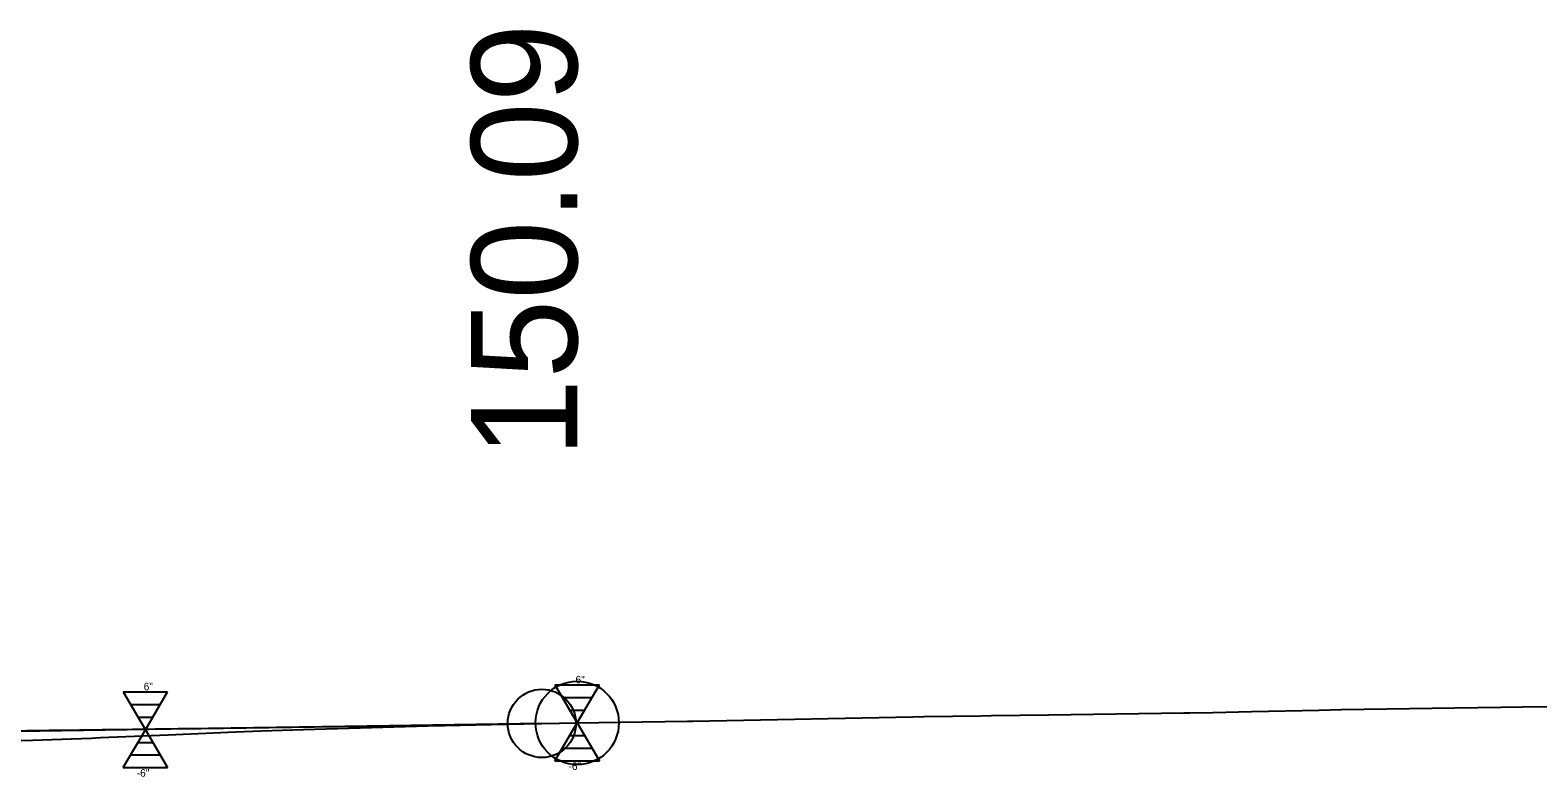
# Model space of a CAD drawing. Extents: x 573468 to 580768, y -57414 to -51768.
# Drawn here: x 575797.7 to 575897.1, y -53383.4 to -53334.2 of the extents above; entities that cross this region are included whole.
import ezdxf

# ---------------------------------------------------------------- set-up
doc = ezdxf.new("R2010")
doc.units = 0
for name, color, linetype in [('Exist Vertical Profile Ground Line', 7, 'Continuous'), ('Pattern 2', 7, 'Continuous'), ('Prop Vertical Profile Curve Label', 7, 'Continuous'), ('Prop Vertical Profile Grade', 7, 'Continuous'), ('Prop VPI Label', 7, 'Continuous')]:
    doc.layers.add(name, color=color, linetype=linetype)

msp = doc.modelspace()

# ---------------------------------------------------------------- linework, layer by layer
at = {"layer": 'Exist Vertical Profile Ground Line'}
msp.add_lwpolyline([(575793.37, -53381.119), (575797.837, -53380.998), (575801.709, -53380.869), (575802.304, -53380.843), (575806.771, -53380.652), (575811.238, -53380.464), (575812.905, -53380.395), (575815.705, -53380.311), (575820.18, -53380.179), (575824.639, -53380.044), (575825.021, -53380.032), (575829.106, -53379.952), (575833.758, -53379.863), (575838.039, -53379.802), (575841.041, -53379.759), (575841.381, -53379.753), (575842.506, -53379.73), (575846.973, -53379.64), (575851.44, -53379.552), (575855.907, -53379.464), (575856.642, -53379.45), (575860.374, -53379.395), (575861.097, -53379.384), (575864.841, -53379.33), (575869.308, -53379.266), (575873.775, -53379.203), (575874.162, -53379.198), (575875.686, -53379.177), (575878.241, -53379.122), (575882.708, -53379.028), (575884.155, -53378.997), (575887.175, -53378.95), (575891.642, -53378.882), (575894.683, -53378.837), (575896.109, -53378.82), (575900.576, -53378.768)], dxfattribs=at)
at = {"layer": 'Pattern 2'}
for p, q in [((575803.811, -53377.818), (575806.744, -53377.818)), ((575803.811, -53377.818), (575805.278, -53380.318)), ((575805.278, -53380.318), (575806.744, -53377.818)), ((575832.291, -53377.368), (575835.224, -53377.368)), ((575832.291, -53377.368), (575833.758, -53379.868)), ((575833.758, -53379.868), (575835.224, -53377.368)), ((575804.3, -53378.652), (575806.255, -53378.652)), ((575832.78, -53378.202), (575834.735, -53378.202)), ((575804.789, -53379.485), (575805.766, -53379.485)), ((575833.269, -53379.035), (575834.246, -53379.035)), ((575803.811, -53382.818), (575805.278, -53380.318)), ((575805.278, -53380.318), (575806.744, -53382.818)), ((575832.291, -53382.368), (575833.758, -53379.868)), ((575833.269, -53380.702), (575834.246, -53380.702)), ((575833.758, -53379.868), (575835.224, -53382.368)), ((575804.789, -53381.152), (575805.766, -53381.152)), ((575832.78, -53381.535), (575834.735, -53381.535)), ((575803.811, -53382.818), (575806.744, -53382.818)), ((575804.3, -53381.985), (575806.255, -53381.985)), ((575832.291, -53382.368), (575835.224, -53382.368))]:
    msp.add_line(p, q, dxfattribs=at)
at = {"layer": 'Prop Vertical Profile Curve Label'}
msp.add_circle((575831.428, -53379.904), 2.25, dxfattribs=at)
at = {"layer": 'Prop Vertical Profile Grade'}
msp.add_line((575831.428, -53379.904), (575833.758, -53379.868), dxfattribs=at)
msp.add_spline([(575431.428, -53379.651), (575439.428, -53379.781), (575447.428, -53379.906), (575455.428, -53380.026), (575463.428, -53380.141), (575471.428, -53380.251), (575479.428, -53380.356), (575487.428, -53380.455), (575495.428, -53380.55), (575503.428, -53380.639), (575511.428, -53380.723), (575519.428, -53380.802), (575527.428, -53380.876), (575535.428, -53380.945), (575543.428, -53381.009), (575551.428, -53381.068), (575559.428, -53381.121), (575567.428, -53381.17), (575575.428, -53381.213), (575583.428, -53381.251), (575591.428, -53381.285), (575599.428, -53381.313), (575607.428, -53381.336), (575615.428, -53381.353), (575623.428, -53381.366), (575631.428, -53381.374), (575639.428, -53381.376), (575647.428, -53381.374), (575655.428, -53381.366), (575663.428, -53381.353), (575671.428, -53381.335), (575679.428, -53381.312), (575687.428, -53381.284), (575695.428, -53381.251), (575703.428, -53381.212), (575711.428, -53381.169), (575719.428, -53381.12), (575727.428, -53381.067), (575735.428, -53381.008), (575743.428, -53380.944), (575751.428, -53380.875), (575759.428, -53380.801), (575767.428, -53380.722), (575775.428, -53380.637), (575783.428, -53380.548), (575791.428, -53380.453), (575799.428, -53380.354), (575807.428, -53380.249), (575815.428, -53380.139), (575823.428, -53380.024), (575831.428, -53379.904)], degree=3, dxfattribs=at)
at = {"layer": 'Prop VPI Label'}
msp.add_line((575831.428, -53379.904), (575634.177, -53382.928), dxfattribs=at)
msp.add_circle((575833.758, -53379.868), 2.75, dxfattribs=at)

# ---------------------------------------------------------------- texts
at = {"layer": 'Pattern 2'}
for s, p in [('6"', (575833.645, -53377.267)), ('6"', (575805.165, -53377.717)), ('-6"', (575833.184, -53382.971)), ('-6"', (575804.704, -53383.421))]:
    msp.add_text(s, height=0.5, rotation=360, dxfattribs=at).set_placement(p)
at = {"layer": 'Prop VPI Label'}
msp.add_text('150.09', height=7, rotation=90, dxfattribs=at).set_placement((575833.758, -53362.368))

doc.saveas('drawing.dxf')
